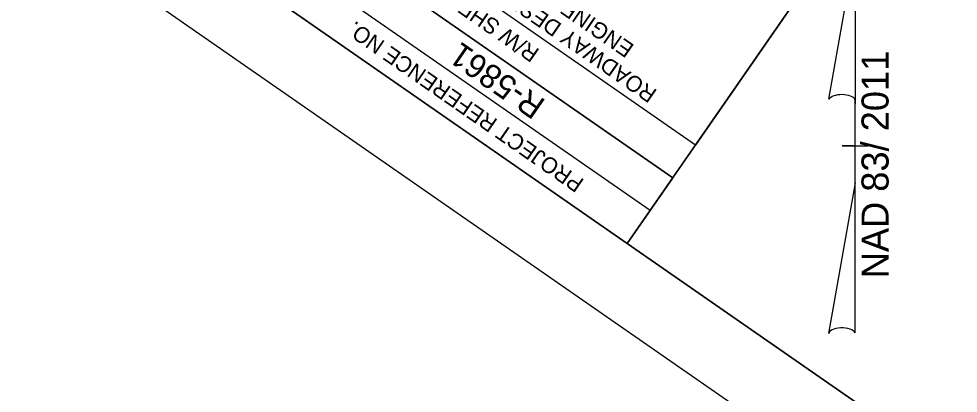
# Model space of a CAD drawing. Extents: x 478372 to 480379, y 492840 to 494699.
# Drawn here: x 478372.1 to 478667.1, y 493647.1 to 493764.6 of the extents above; entities that cross this region are included whole.
import ezdxf

# ---------------------------------------------------------------- set-up
doc = ezdxf.new("R2010")
doc.units = 0
for name, color, linetype in [('Prop North Arrow NAD83 for Plan Sheets CELL', 7, 'Continuous'), ('Sheet Clip Boundary CELL', 7, 'Continuous'), ('Sheet Data Field CELL', 7, 'Continuous'), ('Sheet Plan CELL', 7, 'Continuous'), ('Sheet Plot Border Outside CELL', 7, 'Continuous')]:
    doc.layers.add(name, color=color, linetype=linetype)

msp = doc.modelspace()

# ---------------------------------------------------------------- linework, layer by layer
at = {"layer": 'Prop North Arrow NAD83 for Plan Sheets CELL'}
for p, q in [((478626.5, 493739.35), (478634.7, 493785.7)), ((478634.75, 493785.7), (478634.75, 493737.9)), ((478634.75, 493713.1), (478634.75, 493739.3)), ((478634.75, 493737.9), (478634.75, 493739.25)), ((478630.75, 493724.7), (478630.7, 493724.7)), ((478634.3, 493724.7), (478630.75, 493724.7)), ((478630.8, 493724.7), (478638.8, 493724.7)), ((478634.75, 493713.1), (478626.4, 493665.85)), ((478634.8, 493666.05), (478634.75, 493713.1))]:
    msp.add_line(p, q, dxfattribs=at)
for centre, start_param, end_param in [((478630.64, 493738.85), 0.216388, 2.908219), ((478630.64, 493665.68), 0.201328, 3.141593)]:
    msp.add_ellipse(centre, major_axis=(4.23, -0.03), ratio=0.461098, start_param=start_param, end_param=end_param, dxfattribs=at)
at = {"layer": 'Sheet Clip Boundary CELL'}
msp.add_lwpolyline([(479740.65, 493110.71), (479819.09, 493331.13), (479938.9, 493670.6), (480035.01, 493951.06), (479137.46, 494573.68), (479091.85, 494507.93), (479078.63, 494420.53), (478968.98, 494336.48), (478682.91, 494117.93), (478570.32, 494055.33), (478497.76, 493950.74), (478662.13, 493836.73), (478563.21, 493694.11), (479631.38, 492953.18)], close=True, dxfattribs=at)
at = {"layer": 'Sheet Plan CELL'}
for p, q in [((478577.51, 493714.73), (478413.13, 493828.72)), ((478577.51, 493714.73), (478413.13, 493828.72)), ((478570.37, 493704.42), (478406.01, 493818.45)), ((478577.51, 493714.73), (478584.63, 493724.99))]:
    msp.add_line(p, q, dxfattribs=at)
for points in [[(478398.82, 493808.16), (479631.35, 492953.18), (480229.82, 493815.92), (478997.32, 494670.89)], [(480229.82, 493815.92), (479631.38, 492953.18), (478563.21, 493694.11), (478648.73, 493817.42), (478484.38, 493931.45), (478997.32, 494670.89)], [(478584.63, 493724.99), (478502.42, 493782.01), (478566.55, 493874.46), (478648.73, 493817.42)], [(478563.21, 493694.11), (478398.82, 493808.16), (478413.13, 493828.72), (478577.51, 493714.73)]]:
    msp.add_lwpolyline(points, close=True, dxfattribs=at)
at = {"layer": 'Sheet Plot Border Outside CELL'}
msp.add_lwpolyline([(480379.45, 493739.53), (478996.18, 494699.08), (478372.06, 493799.36), (479755.33, 492839.81)], close=True, dxfattribs=at)

# ---------------------------------------------------------------- texts
at = {"layer": 'Prop North Arrow NAD83 for Plan Sheets CELL'}
msp.add_text('NAD 83/ 2011', height=8.5, rotation=90, dxfattribs=at).set_placement((478645.27, 493683.18))
at = {"layer": 'Sheet Data Field CELL'}
msp.add_text('R-5861', height=7.5, rotation=145.2516, dxfattribs=at).set_placement((478537.92, 493738.82))
at = {"layer": 'Sheet Plan CELL'}
for s, height, p in [('R/W SHEET NO.', 5.0001, (478535.91, 493754.76)), ('ROADWAY DESIGN', 5.0001, (478572.87, 493742.03)), ('ENGINEER', 5, (478565.67, 493756.19)), ('PROJECT REFERENCE NO.', 5.0001, (478549.94, 493713.93))]:
    msp.add_text(s, height=height, rotation=145.2516, dxfattribs=at).set_placement(p)

doc.saveas('drawing.dxf')
